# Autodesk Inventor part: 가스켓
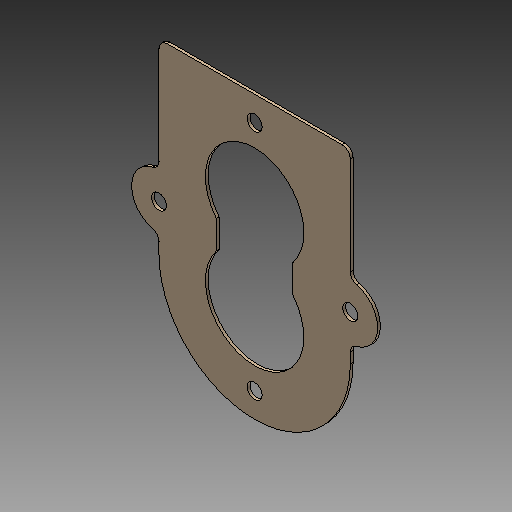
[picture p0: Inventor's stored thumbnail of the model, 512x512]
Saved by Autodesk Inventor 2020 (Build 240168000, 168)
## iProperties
Created: 2024-02
Part Number: 가스켓
Material: 스테인리스강
Document SubType Name: Modeling
Designer: mdu-01
Density: 1 g/cm^3
Appearance: 기본값(1)
Author: mdu-01
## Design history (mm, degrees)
sketch "스케치1"
  geometry: L1 (35, -4.851)-(35, 46) reference; L2 (35, 46)-(15, 46) reference; L3 (15, 37)-(15, 46) reference; L4 (12, 34)-(-12, 34) reference; L5 (-15, 37)-(-15, 46) reference; L6 (-35, 46)-(-15, 46) reference; L7 (-35, -4.851)-(-35, 46) reference; L8 (-35, -34)-(-35, -30.149) reference; L9 (35, -34)-(35, -30.149) reference; L10 (-14, -22.686)-(-14, -12.314) reference; L11 (14, -12.314)-(14, -22.686) reference; L12 (-35, -4.851)-(-35, 31); L13 (-32, 34)-(32, 34); L14 (35, 31)-(35, -4.851); C1 r 10 at (0, -1) reference; C2 r 10 at (0, -34) reference; C3 r 2.067 at (-35, -17.5) reference; C4 r 2.067 at (0, 25) reference; C5 r 2.067 at (0, -60) reference; C6 r 2.067 at (35, -17.5) reference; C7 r 2.75 at (0, 25); C8 r 2.75 at (35, -17.5); C9 r 2.75 at (-35, -17.5); C10 r 2.75 at (0, -60); A1 r 3 centre (12, 37) between (12, 34) and (15, 37) reference; A2 r 3 centre (-12, 37) between (-15, 37) and (-12, 34) reference; A3 r 3 centre (-38, -4.851) between (-37.308, -7.77) and (-35, -4.851) reference; A4 r 10 centre (-35, -17.5) between (-37.308, -7.77) and (-37.308, -27.23) reference; A5 r 3 centre (-38, -30.149) between (-35, -30.149) and (-37.308, -27.23) reference; A6 r 35 centre (0, -34) between (-35, -34) and (35, -34) reference; A7 r 3 centre (38, -30.149) between (37.308, -27.23) and (35, -30.149) reference; A8 r 10 centre (35, -17.5) between (37.308, -27.23) and (37.308, -7.77) reference; A9 r 3 centre (38, -4.851) between (35, -4.851) and (37.308, -7.77) reference; A10 r 18 centre (0, -1) between (14, -12.314) and (-14, -12.314) reference; A11 r 18 centre (0, -34) between (-14, -22.686) and (14, -22.686) reference; A12 r 3 centre (-32, 31) between (-32, 34) and (-35, 31); A13 r 3 centre (32, 31) between (35, 31) and (32, 34); 3 further points
  constraints: 6 centre point, 6 end point, 6 point on line, 6 tangent, 4 coincident, 4 equal radius, 4 point on circle, 2 collinear, 1 perpendicular
  dimensions: "d0" = 3 radius of A12; "d1" = 5.5 diameter of C7
extrude "돌출1" new body sketch "스케치1" distance "d2" = 1; taper "d3" = 0 deg
node "솔리드1"
node "참조1"
node "참조2"
node "참조3"
